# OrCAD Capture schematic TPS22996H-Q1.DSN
size A; title: TPS22996H-Q1 5.5V, 4A, 13mO On-Resistance Dual-Channel; rev: 1.0; note: Datasheet: SLVSHA3A     EVM: SLVUCP0A; note: Synchronous Step Down Converter
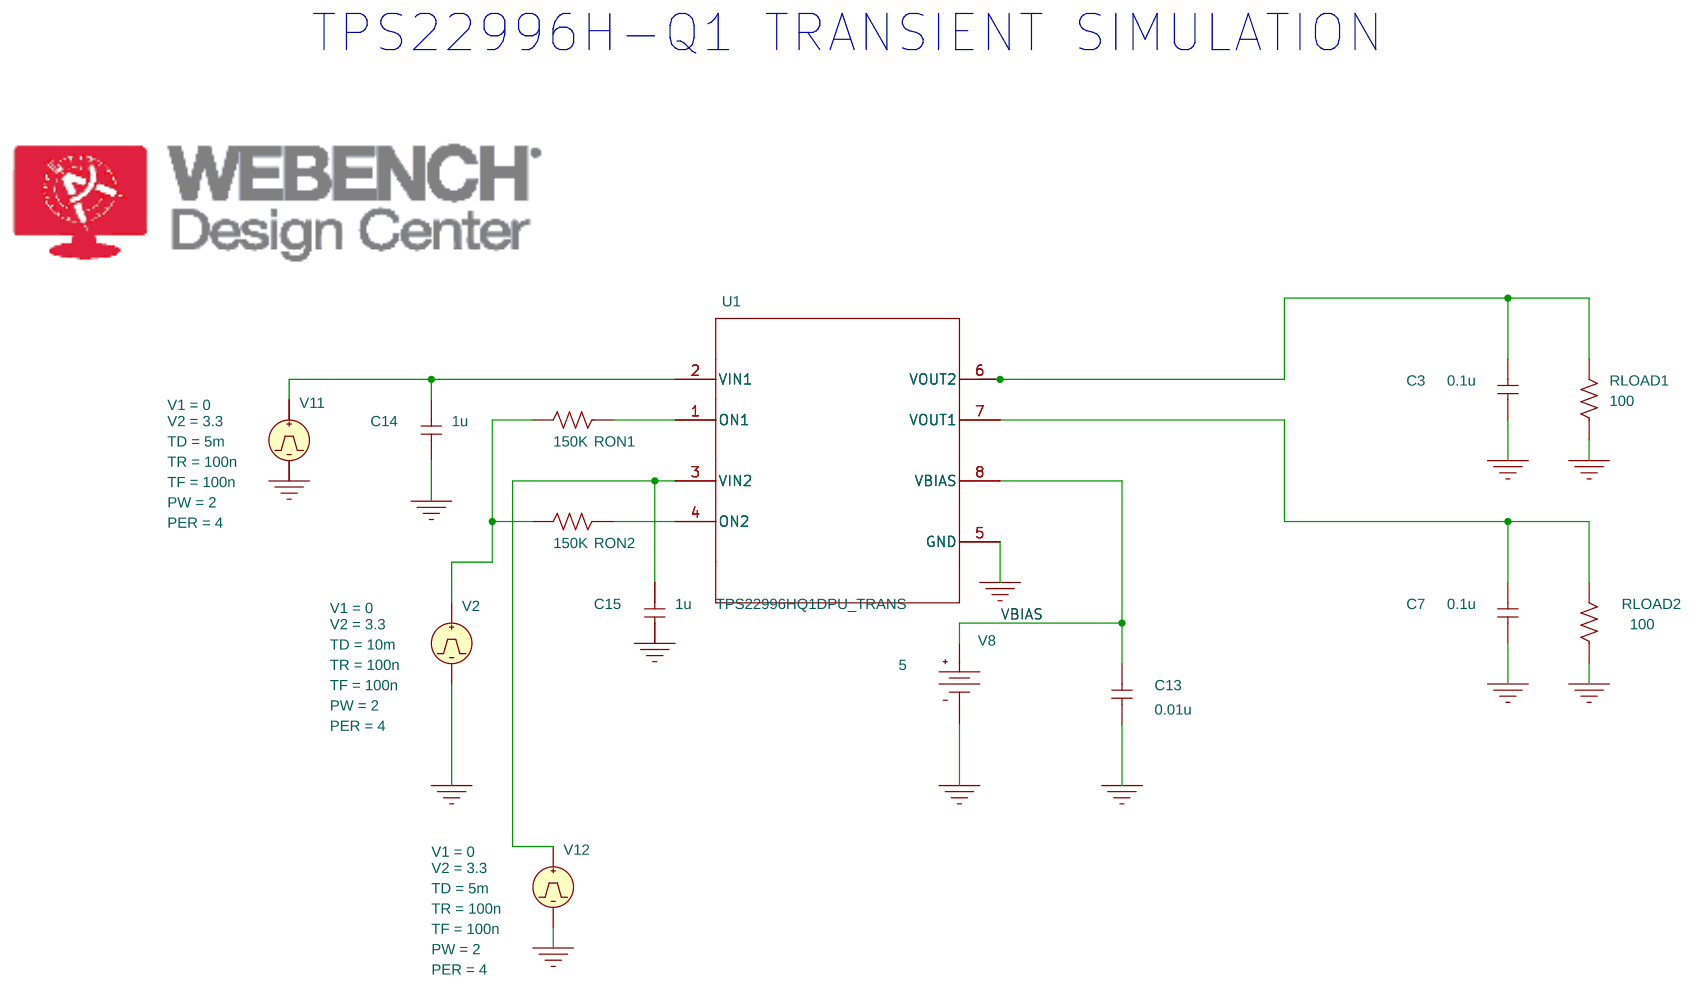
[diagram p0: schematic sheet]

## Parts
C3  0.1u  [RAD/CK05]
C7  0.1u  [RAD/CK05]
C13  0.01u  [RAD/CK05]
C14  1u  [RAD/CK05]
C15  1u  [RAD/CK05]
RLOAD1  100  [AX/RC05]
RLOAD2  100  [AX/RC05]
RON1  150K  [AX/RC05]
RON2  150K  [AX/RC05]
U1  TPS22996HQ1DPU_TRANS  [DPU0014A]
V2  VPULSE
V8  VDC
V11  VPULSE
V12  VPULSE

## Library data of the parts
C3 C7 C14 C15 = C: IC: 0
C13 = C
RLOAD1 RLOAD2 RON1 RON2 = R
U1 = TPS2296HQ1_TRANS
V2 = VPULSE: PER: 4; PW: 2; TD: 10m; TF: 100n; TR: 100n; V1: 0; V2: 3.3
V8 = VDC: DC: 5
V11 V12 = VPULSE: PER: 4; PW: 2; TD: 5m; TF: 100n; TR: 100n; V1: 0; V2: 3.3

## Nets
0: C3.1 C7.1 C13.1 C14.1 C15.1 RLOAD1.1 RLOAD2.1 U1.5(GND) V2.2(-) V8.1(-) V11.2(-) V12.2(-)
VBIAS: C13.2 U1.8(VBIAS) V8.0(+)
N16181745: C14.2 U1.2(VIN1) V11.1(+)
N16181840: C15.2 U1.3(VIN2) V12.1(+)
N16181959: RON1.2 RON2.2 V2.1(+)
N16182227: C3.2 RLOAD1.2 U1.6(VOUT2)
N16182317: C7.2 RLOAD2.2 U1.7(VOUT1)
N16770025: RON1.1 U1.1(ON1)
N16770146: RON2.1 U1.4(ON2)

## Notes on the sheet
- TPS22996H-Q1 TRANSIENT SIMULATION
